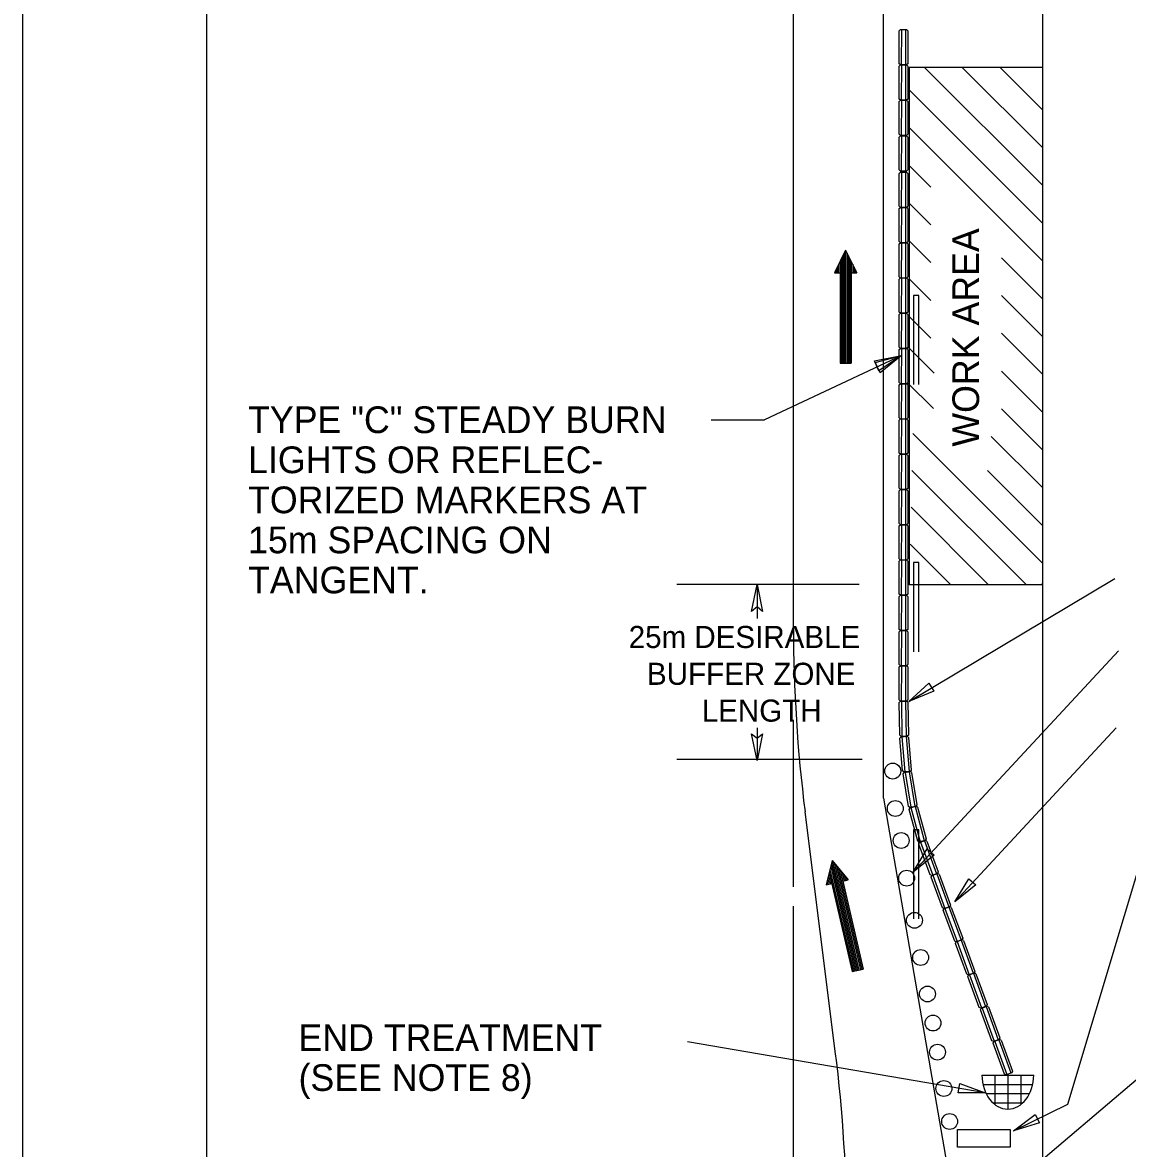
# Model space of a CAD drawing. Extents: x 2179 to 2395, y 134 to 413.
# Drawn here: x 2178.7 to 2238.8, y 294.5 to 355.7 of the extents above; entities that cross this region are included whole.
import ezdxf

# ---------------------------------------------------------------- set-up
doc = ezdxf.new("R2010")
doc.units = 0
for name, color, linetype in [('Level 1', 7, 'Continuous'), ('Level 10', 7, 'Continuous'), ('Level 2', 7, 'Continuous'), ('Level 4', 7, 'Continuous'), ('Level 60', 7, 'Continuous')]:
    doc.layers.add(name, color=color, linetype=linetype)

msp = doc.modelspace()

# ---------------------------------------------------------------- linework, layer by layer
at = {"layer": 'Level 1'}
for p, q in [((2227.137, 340.84), (2227.137, 336.002)), ((2227.427, 340.84), (2227.137, 340.84)), ((2227.427, 336.002), (2227.427, 340.84)), ((2227.137, 326.326), (2227.137, 321.488)), ((2227.427, 326.326), (2227.137, 326.326)), ((2227.427, 321.488), (2227.427, 326.326)), ((2227.137, 311.812), (2227.137, 306.974)), ((2227.427, 311.812), (2227.137, 311.812)), ((2227.427, 306.974), (2227.427, 311.812))]:
    msp.add_line(p, q, dxfattribs=at)
for points in [[(2394.748, 412.757), (2178.748, 412.757), (2178.748, 133.757), (2394.748, 133.757)], [(2375.622, 401.948), (2188.748, 401.948), (2188.748, 144.566), (2375.622, 144.566)]]:
    msp.add_lwpolyline(points, close=True, dxfattribs=at)
at = {"layer": 'Level 10'}
for p, q in [((2234.164, 325.439), (2234.164, 399.283)), ((2225.504, 313.525), (2225.504, 358.27)), ((2220.617, 353.23), (2220.617, 356.607)), ((2220.617, 325.439), (2220.617, 353.23)), ((2234.164, 353.23), (2226.899, 353.23)), ((2226.899, 353.23), (2226.899, 325.113)), ((2234.164, 346.803), (2227.736, 353.23)), ((2234.164, 348.855), (2229.789, 353.23)), ((2234.164, 350.908), (2231.842, 353.23)), ((2234.164, 325.113), (2234.164, 353.23)), ((2231.95, 346.964), (2226.905, 352.008)), ((2232.028, 344.833), (2226.905, 349.956)), ((2228.081, 346.727), (2226.905, 347.903)), ((2234.164, 344.75), (2231.919, 346.995)), ((2228.081, 344.675), (2226.905, 345.851)), ((2234.164, 342.697), (2231.919, 344.942)), ((2228.081, 342.622), (2226.905, 343.798)), ((2223.452, 343.297), (2222.838, 342.07)), ((2223.376, 343.143), (2223.376, 337.161)), ((2223.452, 343.297), (2223.452, 337.161)), ((2223.452, 343.297), (2224.065, 342.07)), ((2223.528, 343.143), (2223.528, 337.161)), ((2223.068, 342.53), (2223.068, 342.07)), ((2223.146, 342.684), (2223.146, 337.161)), ((2223.222, 342.836), (2223.222, 337.161)), ((2223.298, 342.99), (2223.298, 337.161)), ((2223.605, 342.99), (2223.605, 337.161)), ((2223.682, 342.836), (2223.682, 337.161)), ((2223.759, 342.684), (2223.759, 337.161)), ((2223.836, 342.53), (2223.836, 342.07)), ((2234.164, 340.645), (2231.919, 342.89)), ((2222.838, 342.07), (2223.146, 342.07)), ((2222.915, 342.223), (2222.915, 342.07)), ((2222.991, 342.377), (2222.991, 342.07)), ((2223.146, 342.07), (2223.146, 337.161)), ((2223.759, 342.07), (2223.759, 337.161)), ((2223.759, 342.07), (2224.065, 342.07)), ((2223.912, 342.377), (2223.912, 342.07)), ((2223.989, 342.223), (2223.989, 342.07)), ((2228.081, 340.569), (2226.905, 341.745)), ((2234.164, 338.592), (2231.919, 340.837)), ((2228.081, 338.516), (2226.905, 339.693)), ((2234.164, 336.54), (2231.919, 338.784)), ((2228.266, 336.615), (2226.865, 338.016)), ((2226.479, 337.572), (2219.049, 334.087)), ((2223.146, 337.161), (2223.759, 337.161)), ((2234.164, 334.487), (2231.919, 336.731)), ((2228.219, 334.699), (2226.818, 336.1)), ((2234.164, 332.434), (2231.919, 334.679)), ((2216.147, 334.087), (2219.049, 334.087)), ((2234.164, 326.276), (2227.098, 333.342)), ((2234.164, 330.382), (2231.363, 333.183)), ((2233.266, 325.121), (2227.054, 331.334)), ((2234.164, 328.329), (2231.157, 331.336)), ((2231.195, 325.14), (2227.004, 329.332)), ((2229.123, 325.159), (2226.959, 327.322)), ((2220.617, 322.807), (2220.617, 325.95)), ((2226.877, 318.788), (2238.07, 325.456)), ((2234.164, 223.027), (2234.164, 325.439)), ((2234.164, 325.113), (2226.899, 325.113)), ((2234.164, 325.206), (2234.072, 325.114)), ((2227.121, 309.508), (2238.266, 321.536)), ((2220.617, 308.705), (2220.617, 317.776)), ((2229.385, 307.893), (2238.147, 317.348)), ((2225.504, 313.525), (2230.526, 284.563)), ((2222.89, 299.777), (2221.248, 312.785)), ((2235.526, 296.914), (2240.183, 312.477)), ((2222.723, 310.152), (2222.401, 308.818)), ((2222.723, 310.152), (2224.103, 304.174)), ((2222.723, 310.152), (2223.596, 309.094)), ((2222.602, 309.651), (2223.878, 304.122)), ((2222.641, 309.818), (2223.952, 304.139)), ((2222.683, 309.985), (2224.029, 304.157)), ((2222.831, 310.019), (2224.177, 304.191)), ((2222.941, 309.887), (2224.252, 304.208)), ((2223.05, 309.754), (2224.327, 304.225)), ((2223.159, 309.623), (2224.401, 304.243)), ((2222.401, 308.818), (2222.7, 308.887)), ((2222.441, 308.984), (2222.476, 308.836)), ((2222.48, 309.152), (2222.55, 308.852)), ((2222.521, 309.318), (2222.625, 308.87)), ((2222.562, 309.485), (2223.804, 304.105)), ((2222.7, 308.887), (2223.804, 304.105)), ((2223.268, 309.491), (2223.372, 309.042)), ((2223.297, 309.026), (2223.596, 309.094)), ((2223.297, 309.026), (2224.401, 304.243)), ((2223.377, 309.359), (2223.447, 309.059)), ((2223.487, 309.226), (2223.522, 309.077)), ((2220.617, 223.004), (2220.617, 307.66)), ((2223.804, 304.105), (2224.401, 304.243)), ((2231.034, 297.528), (2214.862, 300.297)), ((2232.288, 292.347), (2239.364, 298.329)), ((2232.577, 295.45), (2235.526, 296.914))]:
    msp.add_line(p, q, dxfattribs=at)
for points in [[(2225.011, 337.284), (2226.479, 337.572), (2225.319, 336.627)], [(2225.052, 337.202), (2226.479, 337.572), (2225.263, 336.74)], [(2218.64, 325.131), (2218.942, 323.679), (2218.642, 323.919), (2218.342, 323.679)], [(2228.245, 319.336), (2226.877, 318.788), (2227.978, 319.768)], [(2218.64, 315.573), (2218.339, 317.026), (2218.639, 316.786), (2218.939, 317.026)], [(2228.265, 310.436), (2227.121, 309.508), (2227.881, 310.77)], [(2230.529, 308.822), (2229.385, 307.893), (2230.146, 309.155)], [(2229.646, 298.024), (2231.034, 297.528), (2229.56, 297.523)], [(2233.982, 295.895), (2232.577, 295.45), (2233.748, 296.346)], [(2229.535, 295.532), (2232.396, 295.532), (2232.396, 294.578), (2229.535, 294.578)]]:
    msp.add_lwpolyline(points, close=True, dxfattribs=at)
for centre in [(2226.01, 315.001), (2226.147, 312.969), (2226.465, 311.227), (2226.764, 309.187), (2227.188, 306.896), (2227.523, 304.872), (2227.894, 302.891), (2228.195, 301.313), (2228.441, 299.732), (2228.788, 297.759), (2229.1, 295.963)]:
    msp.add_circle(centre, 0.431, dxfattribs=at)
for centre, start, end in [((2300.617, 322.807), 180, 187.19647), ((2143.52, 289.755), 0, 7.19647)]:
    msp.add_arc(centre, 80, start, end, dxfattribs=at)
at = {"layer": 'Level 2'}
for p, q in [((2224.194, 325.131), (2214.277, 325.131)), ((2218.64, 325.131), (2218.64, 323.282)), ((2218.64, 317.359), (2218.64, 315.714)), ((2224.351, 315.632), (2214.277, 315.632))]:
    msp.add_line(p, q, dxfattribs=at)
at = {"layer": 'Level 4'}
for p, q in [((2226.361, 353.426), (2226.363, 355.214)), ((2226.363, 355.214), (2226.429, 355.279)), ((2226.429, 355.279), (2226.759, 355.279)), ((2226.479, 355.279), (2226.476, 353.362)), ((2226.708, 355.28), (2226.706, 353.36)), ((2226.825, 355.214), (2226.759, 355.279)), ((2226.825, 355.214), (2226.823, 353.426)), ((2226.427, 353.361), (2226.361, 353.426)), ((2226.361, 351.51), (2226.363, 353.297)), ((2226.363, 353.297), (2226.429, 353.362)), ((2226.758, 353.361), (2226.427, 353.361)), ((2226.429, 353.362), (2226.759, 353.362)), ((2226.479, 353.362), (2226.476, 351.445)), ((2226.708, 353.363), (2226.706, 351.444)), ((2226.823, 353.426), (2226.758, 353.361)), ((2226.825, 353.298), (2226.759, 353.362)), ((2226.825, 353.298), (2226.823, 351.509)), ((2226.427, 351.444), (2226.361, 351.51)), ((2226.361, 349.593), (2226.363, 351.381)), ((2226.363, 351.381), (2226.429, 351.446)), ((2226.758, 351.445), (2226.427, 351.444)), ((2226.429, 351.446), (2226.759, 351.446)), ((2226.479, 351.446), (2226.476, 349.529)), ((2226.708, 351.447), (2226.706, 349.527)), ((2226.823, 351.509), (2226.758, 351.445)), ((2226.825, 351.381), (2226.759, 351.446)), ((2226.825, 351.381), (2226.823, 349.593)), ((2226.427, 349.528), (2226.361, 349.593)), ((2226.361, 347.657), (2226.363, 349.445)), ((2226.363, 349.445), (2226.429, 349.51)), ((2226.758, 349.528), (2226.427, 349.528)), ((2226.429, 349.51), (2226.759, 349.51)), ((2226.479, 349.51), (2226.476, 347.593)), ((2226.708, 349.511), (2226.706, 347.591)), ((2226.823, 349.593), (2226.758, 349.528)), ((2226.825, 349.445), (2226.759, 349.51)), ((2226.825, 349.445), (2226.823, 347.657)), ((2226.427, 347.592), (2226.361, 347.657)), ((2226.361, 345.683), (2226.363, 347.471)), ((2226.363, 347.471), (2226.429, 347.536)), ((2226.758, 347.593), (2226.427, 347.592)), ((2226.429, 347.536), (2226.759, 347.535)), ((2226.479, 347.536), (2226.476, 345.618)), ((2226.708, 347.536), (2226.706, 345.617)), ((2226.823, 347.657), (2226.758, 347.593)), ((2226.825, 347.471), (2226.759, 347.535)), ((2226.825, 347.471), (2226.823, 345.682)), ((2226.427, 345.618), (2226.361, 345.683)), ((2226.363, 345.554), (2226.429, 345.619)), ((2226.758, 345.618), (2226.427, 345.618)), ((2226.429, 345.619), (2226.759, 345.619)), ((2226.479, 345.619), (2226.476, 343.702)), ((2226.708, 345.62), (2226.706, 343.7)), ((2226.823, 345.682), (2226.758, 345.618)), ((2226.825, 345.554), (2226.759, 345.619)), ((2226.361, 343.766), (2226.363, 345.554)), ((2226.825, 345.554), (2226.823, 343.766)), ((2226.427, 343.701), (2226.361, 343.766)), ((2226.823, 343.766), (2226.758, 343.702)), ((2226.361, 341.851), (2226.363, 343.639)), ((2226.363, 343.639), (2226.429, 343.704)), ((2226.758, 343.702), (2226.427, 343.701)), ((2226.429, 343.704), (2226.759, 343.704)), ((2226.479, 343.704), (2226.476, 341.787)), ((2226.708, 343.705), (2226.706, 341.785)), ((2226.825, 343.639), (2226.759, 343.704)), ((2226.825, 343.639), (2226.823, 341.851)), ((2226.427, 341.786), (2226.361, 341.851)), ((2226.361, 339.936), (2226.363, 341.724)), ((2226.363, 341.724), (2226.429, 341.789)), ((2226.758, 341.786), (2226.427, 341.786)), ((2226.429, 341.789), (2226.759, 341.788)), ((2226.479, 341.789), (2226.476, 339.871)), ((2226.708, 341.79), (2226.706, 339.87)), ((2226.823, 341.851), (2226.758, 341.786)), ((2226.825, 341.724), (2226.759, 341.788)), ((2226.825, 341.724), (2226.823, 339.936)), ((2226.427, 339.871), (2226.361, 339.936)), ((2226.361, 338.021), (2226.363, 339.809)), ((2226.363, 339.809), (2226.429, 339.874)), ((2226.758, 339.871), (2226.427, 339.871)), ((2226.429, 339.874), (2226.759, 339.873)), ((2226.479, 339.874), (2226.476, 337.956)), ((2226.708, 339.875), (2226.706, 337.955)), ((2226.823, 339.936), (2226.758, 339.871)), ((2226.825, 339.809), (2226.759, 339.873)), ((2226.825, 339.809), (2226.823, 338.02)), ((2226.427, 337.956), (2226.361, 338.021)), ((2226.361, 336.106), (2226.363, 337.894)), ((2226.363, 337.894), (2226.429, 337.959)), ((2226.758, 337.956), (2226.427, 337.956)), ((2226.429, 337.959), (2226.759, 337.958)), ((2226.479, 337.959), (2226.476, 336.041)), ((2226.708, 337.959), (2226.706, 336.04)), ((2226.823, 338.02), (2226.758, 337.956)), ((2226.825, 337.894), (2226.759, 337.958)), ((2226.825, 337.894), (2226.823, 336.105)), ((2226.427, 336.041), (2226.361, 336.106)), ((2226.361, 334.191), (2226.363, 335.979)), ((2226.363, 335.979), (2226.429, 336.044)), ((2226.758, 336.041), (2226.427, 336.041)), ((2226.429, 336.044), (2226.759, 336.043)), ((2226.479, 336.044), (2226.476, 334.126)), ((2226.708, 336.044), (2226.706, 334.125)), ((2226.823, 336.105), (2226.758, 336.041)), ((2226.825, 335.979), (2226.759, 336.043)), ((2226.825, 335.979), (2226.823, 334.19)), ((2226.427, 334.126), (2226.361, 334.191)), ((2226.361, 332.276), (2226.363, 334.063)), ((2226.363, 334.063), (2226.429, 334.128)), ((2226.758, 334.126), (2226.427, 334.126)), ((2226.429, 334.128), (2226.759, 334.128)), ((2226.479, 334.128), (2226.476, 332.211)), ((2226.708, 334.129), (2226.706, 332.21)), ((2226.823, 334.19), (2226.758, 334.126)), ((2226.825, 334.064), (2226.759, 334.128)), ((2226.825, 334.064), (2226.823, 332.275)), ((2226.427, 332.211), (2226.361, 332.276)), ((2226.361, 330.361), (2226.363, 332.148)), ((2226.363, 332.148), (2226.429, 332.213)), ((2226.758, 332.211), (2226.427, 332.211)), ((2226.429, 332.213), (2226.759, 332.213)), ((2226.479, 332.213), (2226.476, 330.296)), ((2226.708, 332.214), (2226.706, 330.295)), ((2226.823, 332.275), (2226.758, 332.211)), ((2226.825, 332.148), (2226.759, 332.213)), ((2226.825, 332.148), (2226.823, 330.36)), ((2226.427, 330.295), (2226.361, 330.361)), ((2226.363, 330.233), (2226.429, 330.298)), ((2226.758, 330.296), (2226.427, 330.295)), ((2226.429, 330.298), (2226.759, 330.298)), ((2226.479, 330.298), (2226.476, 328.381)), ((2226.708, 330.299), (2226.706, 328.38)), ((2226.823, 330.36), (2226.758, 330.296)), ((2226.825, 330.233), (2226.759, 330.298)), ((2226.361, 328.446), (2226.363, 330.233)), ((2226.825, 330.233), (2226.823, 328.445)), ((2226.427, 328.38), (2226.361, 328.446)), ((2226.361, 326.531), (2226.363, 328.318)), ((2226.363, 328.318), (2226.429, 328.383)), ((2226.758, 328.381), (2226.427, 328.38)), ((2226.429, 328.383), (2226.759, 328.383)), ((2226.479, 328.383), (2226.476, 326.466)), ((2226.708, 328.384), (2226.706, 326.465)), ((2226.823, 328.445), (2226.758, 328.381)), ((2226.825, 328.318), (2226.759, 328.383)), ((2226.825, 328.318), (2226.823, 326.53)), ((2226.427, 326.465), (2226.361, 326.531)), ((2226.361, 324.615), (2226.363, 326.403)), ((2226.363, 326.403), (2226.429, 326.468)), ((2226.758, 326.466), (2226.427, 326.465)), ((2226.429, 326.468), (2226.759, 326.468)), ((2226.479, 326.468), (2226.476, 324.551)), ((2226.708, 326.469), (2226.706, 324.549)), ((2226.823, 326.53), (2226.758, 326.466)), ((2226.825, 326.403), (2226.759, 326.468)), ((2226.825, 326.403), (2226.823, 324.615)), ((2226.427, 324.55), (2226.361, 324.615)), ((2226.361, 322.7), (2226.363, 324.488)), ((2226.363, 324.488), (2226.429, 324.553)), ((2226.758, 324.551), (2226.427, 324.55)), ((2226.429, 324.553), (2226.759, 324.553)), ((2226.479, 324.553), (2226.476, 322.636)), ((2226.708, 324.554), (2226.706, 322.634)), ((2226.823, 324.615), (2226.758, 324.551)), ((2226.825, 324.488), (2226.759, 324.553)), ((2226.825, 324.488), (2226.823, 322.7)), ((2226.427, 322.635), (2226.361, 322.7)), ((2226.361, 320.785), (2226.363, 322.573)), ((2226.363, 322.573), (2226.429, 322.638)), ((2226.758, 322.635), (2226.427, 322.635)), ((2226.429, 322.638), (2226.759, 322.638)), ((2226.479, 322.638), (2226.476, 320.72)), ((2226.708, 322.639), (2226.706, 320.719)), ((2226.823, 322.7), (2226.758, 322.635)), ((2226.825, 322.573), (2226.759, 322.638)), ((2226.825, 322.573), (2226.823, 320.785)), ((2226.427, 320.72), (2226.361, 320.785)), ((2226.361, 318.87), (2226.363, 320.658)), ((2226.363, 320.658), (2226.429, 320.723)), ((2226.758, 320.72), (2226.427, 320.72)), ((2226.429, 320.723), (2226.759, 320.722)), ((2226.479, 320.723), (2226.476, 318.805)), ((2226.708, 320.724), (2226.706, 318.804)), ((2226.823, 320.785), (2226.758, 320.72)), ((2226.825, 320.658), (2226.759, 320.722)), ((2226.825, 320.658), (2226.823, 318.869)), ((2226.427, 318.805), (2226.361, 318.87)), ((2226.364, 318.734), (2226.429, 318.8)), ((2226.395, 316.947), (2226.364, 318.734)), ((2226.758, 318.805), (2226.427, 318.805)), ((2226.429, 318.8), (2226.759, 318.806)), ((2226.479, 318.801), (2226.51, 316.884)), ((2226.708, 318.806), (2226.741, 316.887)), ((2226.823, 318.869), (2226.758, 318.805)), ((2226.827, 318.742), (2226.759, 318.806)), ((2226.827, 318.742), (2226.857, 316.954)), ((2226.462, 316.883), (2226.395, 316.947)), ((2226.402, 316.793), (2226.461, 316.864)), ((2226.461, 316.864), (2226.792, 316.891)), ((2226.792, 316.889), (2226.462, 316.883)), ((2226.511, 316.868), (2226.668, 314.957)), ((2226.74, 316.887), (2226.897, 314.975)), ((2226.857, 316.954), (2226.792, 316.889)), ((2226.863, 316.832), (2226.792, 316.891)), ((2226.548, 315.012), (2226.402, 316.793)), ((2226.863, 316.832), (2227.008, 315.05)), ((2226.619, 314.952), (2226.548, 315.012)), ((2227.008, 315.05), (2226.949, 314.98)), ((2226.574, 314.849), (2226.629, 314.924)), ((2226.866, 313.086), (2226.574, 314.849)), ((2226.949, 314.98), (2226.619, 314.952)), ((2226.629, 314.924), (2226.956, 314.978)), ((2226.678, 314.932), (2226.99, 313.04)), ((2226.904, 314.969), (2227.217, 313.076)), ((2227.031, 314.924), (2226.956, 314.978)), ((2227.031, 314.924), (2227.322, 313.161)), ((2226.942, 313.031), (2226.866, 313.086)), ((2226.905, 312.921), (2226.952, 313.001)), ((2227.375, 311.197), (2226.905, 312.921)), ((2227.268, 313.085), (2226.942, 313.031)), ((2226.952, 313.001), (2227.271, 313.088)), ((2227, 313.015), (2227.504, 311.164)), ((2227.221, 313.075), (2227.725, 311.223)), ((2227.322, 313.161), (2227.268, 313.085)), ((2227.352, 313.042), (2227.271, 313.088)), ((2227.352, 313.042), (2227.821, 311.318)), ((2227.457, 311.151), (2227.375, 311.197)), ((2227.427, 311.039), (2227.466, 311.123)), ((2228.047, 309.363), (2227.427, 311.039)), ((2227.776, 311.238), (2227.457, 311.151)), ((2227.466, 311.123), (2227.777, 311.238)), ((2227.513, 311.141), (2228.178, 309.342)), ((2227.728, 311.22), (2228.393, 309.42)), ((2227.821, 311.318), (2227.776, 311.238)), ((2227.861, 311.199), (2227.777, 311.238)), ((2227.861, 311.199), (2228.481, 309.523)), ((2228.481, 309.523), (2228.442, 309.439)), ((2228.132, 309.324), (2228.047, 309.363)), ((2228.094, 309.24), (2228.134, 309.324)), ((2228.714, 307.564), (2228.094, 309.24)), ((2228.442, 309.439), (2228.132, 309.324)), ((2228.134, 309.324), (2228.444, 309.439)), ((2228.18, 309.342), (2228.845, 307.543)), ((2228.396, 309.421), (2229.06, 307.621)), ((2228.529, 309.4), (2228.444, 309.439)), ((2228.529, 309.4), (2229.148, 307.724)), ((2229.148, 307.724), (2229.109, 307.64)), ((2228.8, 307.525), (2228.714, 307.564)), ((2228.755, 307.439), (2228.794, 307.523)), ((2229.375, 305.763), (2228.755, 307.439)), ((2228.794, 307.523), (2229.105, 307.638)), ((2229.109, 307.64), (2228.8, 307.525)), ((2228.841, 307.541), (2229.506, 305.742)), ((2229.056, 307.62), (2229.721, 305.82)), ((2229.189, 307.599), (2229.105, 307.638)), ((2229.189, 307.599), (2229.809, 305.923)), ((2229.458, 305.722), (2229.768, 305.837)), ((2229.77, 305.839), (2229.46, 305.724)), ((2229.853, 305.798), (2229.768, 305.837)), ((2229.809, 305.923), (2229.77, 305.839)), ((2229.46, 305.724), (2229.375, 305.763)), ((2229.418, 305.638), (2229.458, 305.722)), ((2230.038, 303.962), (2229.418, 305.638)), ((2229.504, 305.74), (2230.169, 303.941)), ((2229.72, 305.819), (2230.384, 304.019)), ((2229.853, 305.798), (2230.472, 304.122)), ((2230.433, 304.038), (2230.124, 303.923)), ((2230.128, 303.919), (2230.438, 304.033)), ((2230.39, 304.015), (2231.054, 302.215)), ((2230.472, 304.122), (2230.433, 304.038)), ((2230.523, 303.995), (2230.438, 304.033)), ((2230.523, 303.995), (2231.142, 302.318)), ((2230.124, 303.923), (2230.038, 303.962)), ((2230.088, 303.835), (2230.128, 303.919)), ((2230.708, 302.158), (2230.088, 303.835)), ((2230.174, 303.936), (2230.839, 302.137)), ((2230.793, 302.12), (2230.708, 302.158)), ((2231.103, 302.234), (2230.793, 302.12)), ((2230.814, 302.111), (2231.125, 302.225)), ((2231.076, 302.208), (2231.741, 300.408)), ((2231.142, 302.318), (2231.103, 302.234)), ((2231.209, 302.187), (2231.125, 302.225)), ((2231.209, 302.187), (2231.828, 300.51)), ((2230.775, 302.027), (2230.814, 302.111)), ((2231.395, 300.35), (2230.775, 302.027)), ((2230.861, 302.128), (2231.526, 300.329)), ((2231.48, 300.312), (2231.395, 300.35)), ((2231.79, 300.426), (2231.48, 300.312)), ((2231.501, 300.303), (2231.812, 300.417)), ((2231.763, 300.4), (2232.428, 298.6)), ((2231.828, 300.51), (2231.79, 300.426)), ((2231.896, 300.379), (2231.812, 300.417)), ((2231.896, 300.379), (2232.515, 298.703)), ((2231.461, 300.219), (2231.501, 300.303)), ((2232.082, 298.543), (2231.461, 300.219)), ((2231.547, 300.32), (2232.212, 298.521)), ((2232.167, 298.504), (2232.082, 298.543)), ((2232.477, 298.618), (2232.167, 298.504)), ((2232.515, 298.703), (2232.477, 298.618)), ((2230.857, 298.482), (2233.664, 298.482)), ((2230.911, 297.982), (2233.61, 297.982)), ((2231.56, 298.482), (2231.56, 296.886)), ((2232.26, 298.482), (2232.26, 296.639)), ((2232.96, 298.482), (2232.96, 296.886)), ((2231.084, 297.482), (2233.437, 297.482)), ((2231.447, 296.982), (2233.073, 296.982))]:
    msp.add_line(p, q, dxfattribs=at)
msp.add_ellipse((2232.26, 298.489), major_axis=(0, -1.85), ratio=0.758621, start_param=4.716532, end_param=7.849839, dxfattribs=at)

# ---------------------------------------------------------------- texts
at = {"layer": 'Level 10'}
msp.add_text('WORK AREA', height=1.4514, rotation=90, dxfattribs=at).set_placement((2230.701, 332.627))
for s, height, p in [('TYPE "C" STEADY BURN ', 1.451, (2190.996, 333.361)), ('LIGHTS OR REFLEC-', 1.451, (2190.996, 331.185)), ('TORIZED MARKERS AT ', 1.451, (2190.996, 329.009)), ('15m SPACING ON ', 1.451, (2190.996, 326.833)), ('TANGENT.', 1.451, (2190.996, 324.657)), ('END TREATMENT', 1.45, (2193.739, 299.797)), ('(SEE NOTE 8)', 1.45, (2193.739, 297.627))]:
    msp.add_text(s, height=height, dxfattribs=at).set_placement(p)
at = {"layer": 'Level 60'}
for s, p in [('25m DESIRABLE', (2211.669, 321.686)), ('BUFFER ZONE', (2212.661, 319.686)), ('LENGTH', (2215.637, 317.686))]:
    msp.add_text(s, height=1.2, rotation=359.99999, dxfattribs=at).set_placement(p)

doc.saveas('drawing.dxf')
